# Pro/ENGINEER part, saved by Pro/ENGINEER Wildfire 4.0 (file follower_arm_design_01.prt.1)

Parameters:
  METRIC = "NO"

Other parameters: PITCH, DRILL_DIAMETER, THREAD_DIAMETER, THREADS_PER_INCH, THREAD_DEPTH, THREAD_LENGTH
